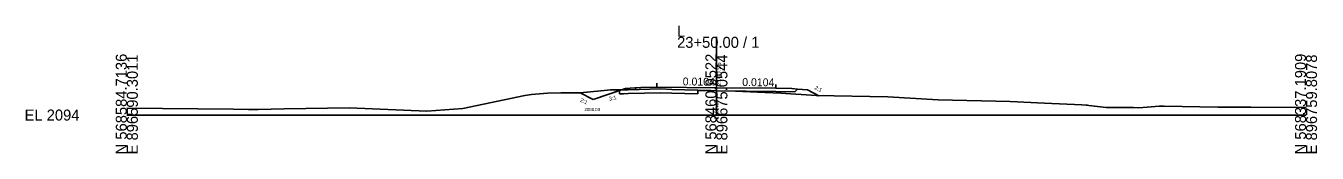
# Model space of a CAD drawing. Extents: x -26 to 1603, y -10 to 13527.
# Drawn here: x -25.7 to 302.8, y 10990.3 to 11022.7 of the extents above; entities that cross this region are included whole.
import ezdxf

# ---------------------------------------------------------------- set-up
doc = ezdxf.new("R2010")
doc.units = 0
for name, color, linetype in [('Default', 7, 'Continuous'), ('Exist XS Center Line Elevation Label', 7, 'Continuous'), ('Exist XS Ground Line', 7, 'Continuous'), ('Old_Level_61', 7, 'Continuous'), ('Old_Level_63', 7, 'Continuous'), ('Prop XS Ditch Slope Text', 7, 'Continuous'), ('Prop XS Ditch Standard Text', 7, 'Continuous'), ('Prop XS Earthwork Shape', 7, 'Continuous'), ('Prop XS EOT Tick Mark', 7, 'Continuous'), ('Prop XS Finish Grade', 7, 'Continuous'), ('Prop XS Finish Grade Earthwork', 7, 'Continuous'), ('Prop XS Finish Grade Paved Shoulder', 7, 'Continuous'), ('Prop XS Finish Grade Pavement', 7, 'Continuous'), ('Prop XS Side Slope Text', 7, 'Continuous'), ('Prop XS Subgrade Earthwork', 7, 'Continuous'), ('Prop XSC Text', 7, 'Continuous')]:
    doc.layers.add(name, color=color, linetype=linetype)

msp = doc.modelspace()

# ---------------------------------------------------------------- linework, layer by layer
at = {"layer": 'Exist XS Ground Line'}
for p, q in [((115.25, 11005.62), (120.58, 11006.12)), ((120.58, 11006.12), (122.3, 11006.31)), ((122.3, 11006.31), (123.06, 11006.39)), ((123.06, 11006.39), (124.11, 11006.39)), ((124.11, 11006.39), (125.38, 11006.4)), ((125.38, 11006.4), (127.57, 11006.45)), ((127.57, 11006.45), (135.82, 11006.63)), ((135.82, 11006.63), (138.64, 11006.53)), ((138.64, 11006.53), (145.25, 11006.37)), ((145.25, 11006.37), (148.54, 11006.21)), ((148.54, 11006.21), (150, 11006.17)), ((150, 11006.17), (154.89, 11006.05)), ((154.89, 11006.05), (160.43, 11005.8)), ((85.49, 11001.67), (101.26, 11004.97)), ((101.26, 11004.97), (102.96, 11005.27)), ((102.96, 11005.27), (107.03, 11005.59)), ((107.03, 11005.59), (110.44, 11005.69)), ((110.44, 11005.69), (115.25, 11005.62)), ((160.43, 11005.8), (166.35, 11005.55)), ((166.35, 11005.55), (175.4, 11004.94)), ((175.4, 11004.94), (193.63, 11004.66)), ((193.63, 11004.66), (206.39, 11003.84)), ((206.39, 11003.84), (224.71, 11003.45)), ((224.71, 11003.45), (233.48, 11003.03)), ((233.48, 11003.03), (242.98, 11002.58)), ((242.98, 11002.58), (244.05, 11002.55)), ((0, 11001.74), (27.1, 11001.48)), ((27.1, 11001.48), (30.94, 11001.43)), ((30.94, 11001.43), (31.83, 11001.44)), ((31.83, 11001.44), (33.39, 11001.38)), ((33.39, 11001.38), (40.07, 11001.56)), ((40.07, 11001.56), (56.55, 11001.86)), ((56.55, 11001.86), (76.36, 11001)), ((76.36, 11001), (85.49, 11001.67)), ((244.05, 11002.55), (244.4, 11002.52)), ((244.4, 11002.52), (244.75, 11002.47)), ((244.75, 11002.47), (249.18, 11001.89)), ((249.18, 11001.89), (256.08, 11001.9)), ((256.08, 11001.9), (257.48, 11001.85)), ((257.48, 11001.85), (259.56, 11002.01)), ((259.56, 11002.01), (262.65, 11002.25)), ((262.65, 11002.25), (263.2, 11002.29)), ((263.2, 11002.29), (263.95, 11002.28)), ((263.95, 11002.28), (277.55, 11002.04)), ((277.55, 11002.04), (285.93, 11001.99)), ((285.93, 11001.99), (298.91, 11001.95)), ((298.91, 11001.95), (300, 11001.96))]:
    msp.add_line(p, q, dxfattribs=at)
at = {"layer": 'Old_Level_61'}
for p, q in [((125.38, 11006.4), (125.38, 11005.4)), ((145.26, 11005.37), (145.26, 11006.37)), ((125.38, 11005.4), (126.4, 11005.42)), ((126.4, 11005.42), (127.57, 11005.45)), ((127.57, 11005.45), (135.82, 11005.63)), ((135.82, 11005.63), (138.64, 11005.53)), ((138.64, 11005.53), (145.25, 11005.37)), ((145.25, 11005.37), (145.26, 11005.37))]:
    msp.add_line(p, q, dxfattribs=at)
at = {"layer": 'Old_Level_63'}
for p, q in [((150, 11000), (150, 11019.9)), ((0, 11000), (150, 11000)), ((150, 11000), (300, 11000))]:
    msp.add_line(p, q, dxfattribs=at)
at = {"layer": 'Prop XS Earthwork Shape'}
for points in [[(118.65, 11004), (115.32, 11005.63), (120.58, 11006.12), (122.3, 11006.31), (123.06, 11006.39), (124.11, 11006.39), (125.38, 11006.4), (125.89, 11006.41)], [(129.65, 11006.49), (129.21, 11006.92), (126.85, 11006.73), (125.89, 11006.41), (127.57, 11006.45)], [(145.26, 11006.22), (145.26, 11006.37), (148.54, 11006.21), (150, 11006.17)], [(173.15, 11006.4), (176.09, 11004.93), (175.4, 11004.94), (166.35, 11005.55), (160.43, 11005.8), (154.89, 11006.05), (150, 11006.17), (165.15, 11006.01), (169.96, 11005.91), (170.64, 11006.6)]]:
    msp.add_lwpolyline(points, close=True, dxfattribs=at)
at = {"layer": 'Prop XS EOT Tick Mark'}
for p, q in [((134.85, 11007.12), (134.85, 11008.12)), ((165.15, 11006.8), (165.15, 11007.8))]:
    msp.add_line(p, q, dxfattribs=at)
at = {"layer": 'Prop XS Finish Grade'}
for p, q in [((130.75, 11007.04), (129.21, 11006.92)), ((169.15, 11006.72), (170.64, 11006.6))]:
    msp.add_line(p, q, dxfattribs=at)
at = {"layer": 'Prop XS Finish Grade Earthwork'}
for p, q in [((126.85, 11006.73), (118.65, 11004)), ((129.21, 11006.92), (126.85, 11006.73)), ((170.64, 11006.6), (173.15, 11006.4)), ((173.15, 11006.4), (176.09, 11004.93)), ((118.65, 11004), (115.32, 11005.63))]:
    msp.add_line(p, q, dxfattribs=at)
at = {"layer": 'Prop XS Finish Grade Paved Shoulder'}
for p, q in [((134.85, 11007.12), (130.75, 11007.04)), ((165.15, 11006.8), (169.15, 11006.72))]:
    msp.add_line(p, q, dxfattribs=at)
at = {"layer": 'Prop XS Finish Grade Pavement'}
for p, q in [((134.85, 11007.12), (150, 11006.96)), ((150, 11006.96), (165.15, 11006.8))]:
    msp.add_line(p, q, dxfattribs=at)
at = {"layer": 'Prop XS Subgrade Earthwork'}
for p, q in [((129.65, 11006.49), (129.21, 11006.92)), ((145.26, 11006.22), (145.26, 11006.37)), ((150, 11006.17), (145.26, 11006.22)), ((165.15, 11006.01), (150, 11006.17)), ((165.15, 11006.01), (169.96, 11005.91)), ((169.96, 11005.91), (170.64, 11006.6))]:
    msp.add_line(p, q, dxfattribs=at)

# ---------------------------------------------------------------- texts
at = {"layer": 'Default'}
for p in [(141.42, 11007.55), (156.56, 11007.39)]:
    msp.add_text('0.0104', height=2, rotation=359.4031, dxfattribs=at).set_placement(p)
at = {"layer": 'Exist XS Center Line Elevation Label'}
msp.add_text('2100.17', height=1, rotation=90, dxfattribs=at).set_placement((150.5, 10998.89))
at = {"layer": 'Old_Level_63'}
for s, p in [('L', (140, 11019.9)), ('23+50.00 / 1', (140, 11017.1)), ('EL 2094', (-26, 10998.6))]:
    msp.add_text(s, height=2.8, dxfattribs=at).set_placement(p)
for s, p in [('N 568584.7136', (0, 10990)), ('E 896590.3011', (2.8, 10990)), ('N 568460.9522', (150, 10990)), ('E 896675.0544', (152.8, 10990)), ('N 568337.1909', (300, 10990)), ('E 896759.8078', (302.8, 10990))]:
    msp.add_text(s, height=2.8, rotation=90, dxfattribs=at).set_placement(p)
at = {"layer": 'Prop XS Ditch Slope Text'}
msp.add_text('3:1', height=1, rotation=13.6791, dxfattribs=at).set_placement((122.78, 11003.62))
at = {"layer": 'Prop XS Ditch Standard Text'}
msp.add_text('2098.00', height=0.8, dxfattribs=at).set_placement((116.41, 11001.01))
at = {"layer": 'Prop XS Side Slope Text'}
for rotation, p in [(333.4349, (174.87, 11006.66)), (334.0285, (115.24, 11003.48))]:
    msp.add_text('2:1', height=1, rotation=rotation, dxfattribs=at).set_placement(p)
at = {"layer": 'Prop XSC Text'}
msp.add_text(' 2100.96', height=1.2, rotation=90, dxfattribs=at).set_placement((151.2, 11006.96))

doc.saveas('drawing.dxf')
